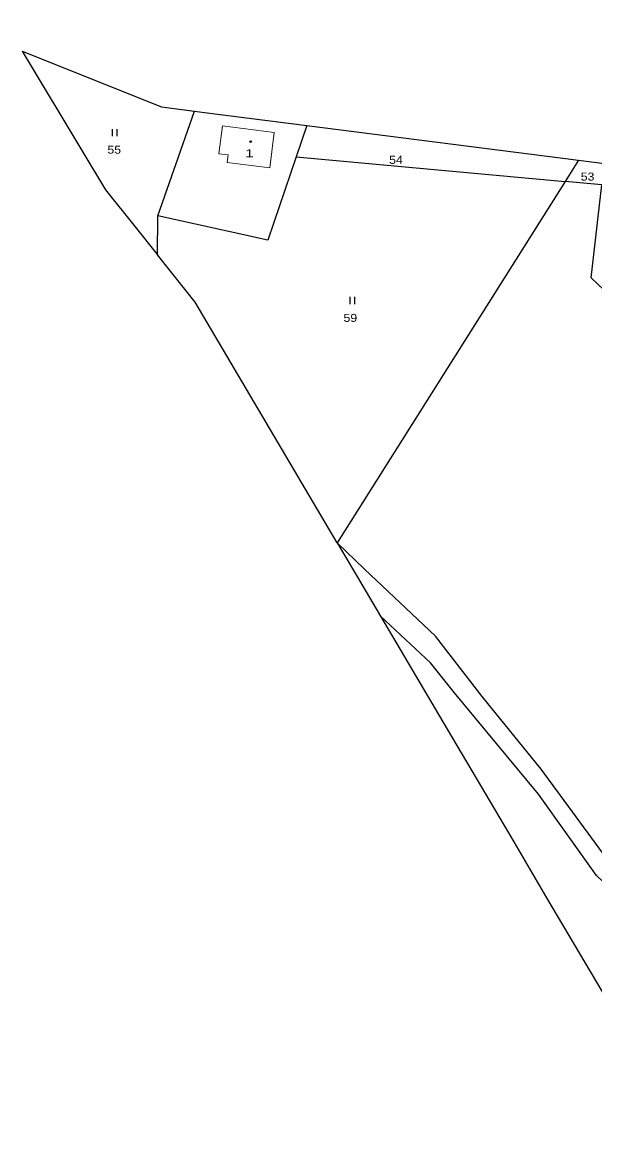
# Model space of a CAD drawing. Extents: x -632162 to -629607, y -1101195 to -1098670.
# Drawn here: x -632162.5 to -632040.8, y -1099401.2 to -1099165 of the extents above; entities that cross this region are included whole.
import ezdxf
from ezdxf.enums import TextEntityAlignment as Align

# ---------------------------------------------------------------- set-up
doc = ezdxf.new("R2010")
doc.units = 0
doc.header["$LTSCALE"] = 0.68
for name, color, linetype, lineweight in [('1', 7, 'Continuous', 25), ('3', 7, 'Continuous', 25), ('4', 7, 'Continuous', 13), ('5', 7, 'Continuous', 25)]:
    doc.layers.add(name, color=color, linetype=linetype, lineweight=lineweight)
doc.layers.add('2', color=7, linetype='Continuous')

msp = doc.modelspace()

# ---------------------------------------------------------------- linework, layer by layer
at = {"layer": '1'}
for p, q in [((-632162.46, -1099171.22), (-632132.88, -1099183.03)), ((-632132.88, -1099183.03), (-632125.84, -1099183.93)), ((-632125.84, -1099183.93), (-632123.73, -1099184.2)), ((-632044.3, -1099194.37), (-632047.15, -1099198.89))]:
    msp.add_line(p, q, dxfattribs=at)
for points in [[(-632123.73, -1099184.2), (-632102.04, -1099186.98), (-632044.3, -1099194.37), (-632038.8, -1099195.05), (-632022.59, -1099197.06), (-631982.3, -1099119.85)], [(-632162.46, -1099171.22), (-632149.56, -1099192.63), (-632144.74, -1099200.64), (-632138.47, -1099208.53), (-632133.74, -1099214.48), (-632133.63, -1099206.13), (-632125.84, -1099183.93)], [(-632102.04, -1099186.98), (-632104.3, -1099193.66), (-632047.15, -1099198.89)], [(-632104.3, -1099193.66), (-632110.26, -1099211.3), (-632133.63, -1099206.13)], [(-631995.89, -1099259.41), (-632010.96, -1099245.45), (-632026.36, -1099233.77), (-632041.61, -1099219.33), (-632039.33, -1099199.61), (-632047.15, -1099198.89), (-632095.57, -1099275.62)], [(-632095.57, -1099275.62), (-632125.75, -1099224.53), (-632133.74, -1099214.48)], [(-632023.01, -1099358.35), (-632037.36, -1099343.98), (-632052.23, -1099323.68), (-632064.78, -1099308.27), (-632074.67, -1099295.42), (-632089.78, -1099281.23), (-632095.57, -1099275.62), (-632090.35, -1099284.46), (-632086.36, -1099291.21)], [(-632086.36, -1099291.21), (-632073.13, -1099313.62), (-632058.06, -1099339.17), (-632051.08, -1099351.01), (-632038.22, -1099372.81), (-632017.33, -1099406.64), (-632014.07, -1099411.91), (-632013.3, -1099413.15), (-631994.37, -1099443.81), (-631964.49, -1099395.7)], [(-631964.49, -1099395.7), (-631977.68, -1099389.37), (-631997.33, -1099384.09), (-632008.27, -1099376.59), (-632014.21, -1099371.19), (-632040.5, -1099346.29), (-632052.83, -1099329.05), (-632070.62, -1099307.47), (-632075.72, -1099301.14), (-632086.36, -1099291.21)]]:
    msp.add_lwpolyline(points, dxfattribs=at)
at = {"layer": '3'}
for p, q in [((-632143.261, -1099189.26), (-632143.261, -1099187.76)), ((-632142.26, -1099189.26), (-632142.26, -1099187.76)), ((-632092.831, -1099224.9), (-632092.831, -1099223.4)), ((-632091.83, -1099224.9), (-632091.83, -1099223.4))]:
    msp.add_line(p, q, dxfattribs=at)
at = {"layer": '4'}
for p, q in [((-632120.7, -1099192.97), (-632119.93, -1099187.02)), ((-632119.93, -1099187.02), (-632108.92, -1099188.44)), ((-632109.89, -1099196), (-632108.92, -1099188.44)), ((-632120.7, -1099192.97), (-632118.72, -1099193.23)), ((-632118.93, -1099194.84), (-632118.72, -1099193.23)), ((-632118.93, -1099194.84), (-632109.89, -1099196))]:
    msp.add_line(p, q, dxfattribs=at)
at = {"layer": '5'}
msp.add_circle((-632113.9368, -1099190.3992), 0.175, dxfattribs=at)

# ---------------------------------------------------------------- texts
at = {"layer": '2'}
for s, width, p in [('55', 1.15, (-632142.92, -1099192.96)), ('1', 1.45, (-632114.2, -1099193.74)), ('54', 1.15, (-632083.07, -1099195.12)), ('53', 1.15, (-632042.38, -1099198.68)), ('59', 1.15, (-632092.77, -1099228.7))]:
    msp.add_text(s, height=1.7, dxfattribs=dict(at, width=width)).set_placement(p, align=Align.CENTER)

doc.saveas('drawing.dxf')
